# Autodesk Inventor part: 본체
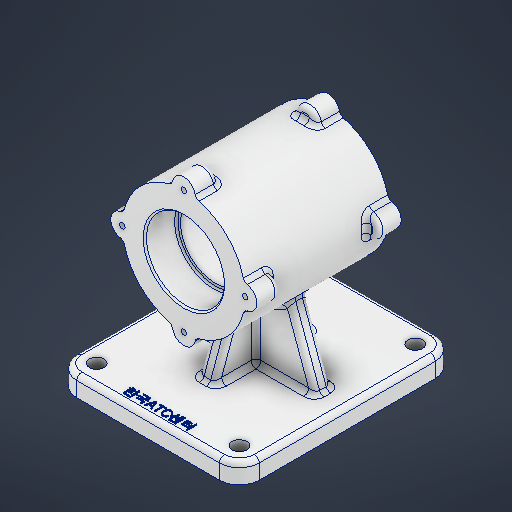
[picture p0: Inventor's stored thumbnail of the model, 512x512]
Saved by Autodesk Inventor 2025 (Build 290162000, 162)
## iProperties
Created: 2025-08
Part Number: 본체
Material: 알루미늄 6061
Document SubType Name: Modeling
Designer: infra027
Density: 2.7 g/cm^3
Appearance: 알루미늄 - 평지
Author: infra027
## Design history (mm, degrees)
sketch "스케치1"
  geometry: L1 (55, -65)-(-55, -65); L2 (-55, -65)-(-55, 65); L3 (-55, 65)-(55, 65); L4 (55, 65)-(55, -65); L5 (55, -65)-(-55, 65); L6 (-55, -65)-(55, 65); L7 (43, 53)-(-43, 53); L8 (-43, 53)-(-43, -53); L9 (-43, -53)-(43, -53); L10 (43, -53)-(43, 53); L11 (43, 53)-(-43, -53); L12 (-43, 53)-(43, -53); C1 r 4.5 at (43, -53); C2 r 4.5 at (-43, 53); C3 r 4.5 at (-43, -53); C4 r 4.5 at (43, 53); 1 further point
  constraints: 25 end point, 4 centre point, 4 midpoint, 4 parallel, 3 coincident, 2 horizontal, 2 perpendicular
  dimensions: "d0" = 130 distance between parallel lines of L1 L3; "d1" = 110 distance between parallel lines of L2 L4; "d2" = 86 distance of L9.end L8.end; "d3" = 106 distance of L8.end L7.end; "d4" = 9 diameter of C1; "d5" = 9 diameter of C2; "d6" = 9 diameter of C3; "d7" = 9 diameter of C4
extrude "돌출1" new body sketch "스케치1" distance "d8" = 12; taper "d9" = 0 deg
sketch "스케치2"
  geometry: L1 (82, 43.5)-(105.5, 43.5); L2 (105.5, 43.5)-(105.5, 24.5); L3 (105.5, 24.5)-(82, 24.5); L4 (82, 24.5)-(82, 43.5); L5 (0, 65)-(0, -65) reference; L6 (82, 24.5)-(103, 24.5); L7 (103, 24.5)-(103, -24.5); L8 (103, -24.5)-(82, -24.5); L9 (82, -24.5)-(82, 24.5); L10 (82, -24.5)-(105.5, -24.5); L11 (105.5, -24.5)-(105.5, -43.5); L12 (105.5, -43.5)-(82, -43.5); L13 (82, -43.5)-(82, -24.5); L14 (82, 43.5)-(119, 43.5); L15 (119, 43.5)-(119, -43.5); L16 (119, -43.5)-(82, -43.5); L17 (82, -43.5)-(82, 43.5); 7 further points
  constraints: 32 end point, 8 parallel, 4 horizontal, 4 perpendicular, 2 midpoint
  dimensions: "d10" = 82 distance between parallel lines of L5 L4; "d11" = 19 distance between parallel lines of L3 L14; "d12" = 19 distance between parallel lines of L12 L10; "d13" = 87 distance between parallel lines of L16 L14; "d14" = 0 vertical distance of point (82, 0) point (0, 0); "d15" = 23.5 distance between parallel lines of L4 L2; "d16" = 23.5 distance between parallel lines of L13 L11 (= d15); "d17" = 21 distance between parallel lines of L9 L7; "d18" = 37 distance between parallel lines of L9 L15
revolve "회전1" sketch "스케치2" stored, may be unused: angle "d19" = 90 deg
sketch "스케치3"
  geometry: C1 r 7 at (0, 37); C2 r 7 at (37, 0); C3 r 7 at (0, -37); C4 r 7 at (-37, 0); A1 r 37 centre (0, 0) between (0, 37) and (37, 0) reference; 9 further points
  constraints: 4 centre point, 4 point on circle, 2 horizontal alignment, 2 vertical alignment
  dimensions: "d20" = 14 diameter of C1; "d21" = 14 diameter of C2; "d22" = 14 diameter of C3; "d23" = 14 diameter of C4
extrude "돌출2" join sketch "스케치3" distance "d24" = 14; taper "d25" = 0 deg
sketch "스케치4"
  geometry: A1 r 37 centre (0, 37) between (6.969, 73.338) and (-6.969, 73.338) reference; A2 r 7 centre (0, 74) between (6.969, 73.338) and (-6.969, 73.338) reference; A3 r 7 centre (37, 37) between (36.338, 30.031) and (36.338, 43.969) reference; A4 r 37 centre (0, 37) between (36.338, 30.031) and (36.338, 43.969) reference; A5 r 7 centre (0, 0) between (-6.969, 0.662) and (6.969, 0.662) reference; A6 r 37 centre (0, 37) between (-6.969, 0.662) and (6.969, 0.662) reference; A7 r 7 centre (-37, 37) between (-36.338, 43.969) and (-36.338, 30.031) reference; A8 r 37 centre (0, 37) between (-36.338, 43.969) and (-36.338, 30.031) reference; 1 further point
hole "구멍1" sketch "스케치4" at (0, 74), (37, 37), (0, 0), (-37, 37) diameter "d26" = 3.242; stored, may be unused: countersink angle "d30" = 90 deg, drill point angle "d32" = 118 deg; dims "d27" = 8, "d28" = 4, "d29" = 2, "d31" = 10
sketch "스케치12"
  geometry: L1 (45, -29.5)-(45, 29.5) reference; L2 (45, 17.989)-(12, 30); L3 (12, 65)-(12, -65) reference; L4 (45, -17.989)-(12, -30); L5 (45, 0)-(12, 0); 1 further point
  constraints: 6 end point, 4 point on line, 2 midpoint, 1 horizontal
  dimensions: "d72" = 110 deg angle of L3 L2; "d73" = 60 distance of L4.end L2.end; "d74" = 110 deg angle of L3 L4; "d75" = 30 distance of L4.end L5.end
sketch "스케치13"
  geometry: L1 (-5, -5)-(5, -5); L2 (5, -5)-(5, 5); L3 (5, 5)-(-5, 5); L4 (-5, 5)-(-5, -5); L5 (-5, -5)-(5, 5); L6 (5, -5)-(-5, 5); 1 further point
  constraints: 12 end point, 2 midpoint, 2 parallel, 1 horizontal, 1 perpendicular
  dimensions: "d76" = 10 distance of L3.end L2.end; "d77" = 10 distance of L2.end L1.end
extrude "돌출5" join sketch "스케치13" stored distance "d78" = 10; taper "d79" = 0 deg
feature "리브3" dims "d80" = 1, "d81" = 10, "d82" = 0, "d83" = 0, "d84" = 1, "d85" = 1
feature "리브4" dims "d86" = 1, "d87" = 10, "d88" = 0, "d89" = 0, "d90" = 1, "d91" = 1
sketch "스케치14"
  geometry: L1 (25.336, 55.036)-(41, 12); L2 (38.5, 12)-(47.5, 12) reference; L3 (55, 0)-(55, 12) reference; L4 (-55, 12)-(55, 12) reference; L5 (-25.336, 55.036)-(-41, 12); L6 (-55, 0)-(-55, 12) reference; A1 r 37 centre (0, 82) between (6.969, 45.662) and (36.338, 75.031) reference; A2 r 37 centre (0, 82) between (-36.338, 75.031) and (-6.969, 45.662) reference; 1 further point
  constraints: 4 end point, 2 point on circle, 2 point on line
  dimensions: "d92" = 14 distance from line of L1.end L3; "d93" = 110 deg angle of L4 L1; "d94" = 14 distance from line of L6 L5.end; "d95" = 110 deg angle of L4 L5
feature "리브5" dims "d96" = 1, "d97" = 10, "d98" = 0, "d99" = 0, "d100" = 1, "d101" = 1
feature "리브6" dims "d102" = 1, "d103" = 10, "d104" = 0, "d105" = 0, "d106" = 1, "d107" = 1
fillet "모깎기1" dims "d108" = 12
fillet "모깎기2" dims "d109" = 3
fillet "모깎기3" dims "d110" = 3
fillet "모깎기4" dims "d111" = 3
fillet "모깎기5" dims "d112" = 1
chamfer "모따기1" distance "d113" = 1; stored, may be unused: second distance "d114" = 2, angle "d115" = 45 deg
chamfer "모따기2" distance "d116" = 1; stored, may be unused: second distance "d117" = 2, angle "d118" = 45 deg
sketch "스케치15" dims "d0" = 130, "d1" = 110
  geometry: L1 (-3.033, -54.998)-(3.033, -54.998); L2 (3.033, -54.998)-(3.033, -61.002); L3 (3.033, -61.002)-(-3.033, -61.002); L4 (-3.033, -61.002)-(-3.033, -54.998); 3 further points
  constraints: 2 midpoint, 1 vertical alignment, 2 other
  dimensions: "d119" = 58 vertical distance of point (3.033, -58) point (0, 0)
feature "엠보싱1" sketch "스케치15" dims "d0" = 130, "d1" = 110, "d120" = 0.5, "d121" = 0
node "솔리드1"
mirror "미러1"
mirror "미러2"
feature "A9D066F2-1C7D-4E18-AEED-F7BC21143FA4" dims "d26" = 3.242, "d27" = 8, "d28" = 4, "d29" = 2, "d30" = 90 deg, "d31" = 10, "d32" = 118 deg
